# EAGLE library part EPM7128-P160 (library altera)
EPM70128 MAX 7000 family
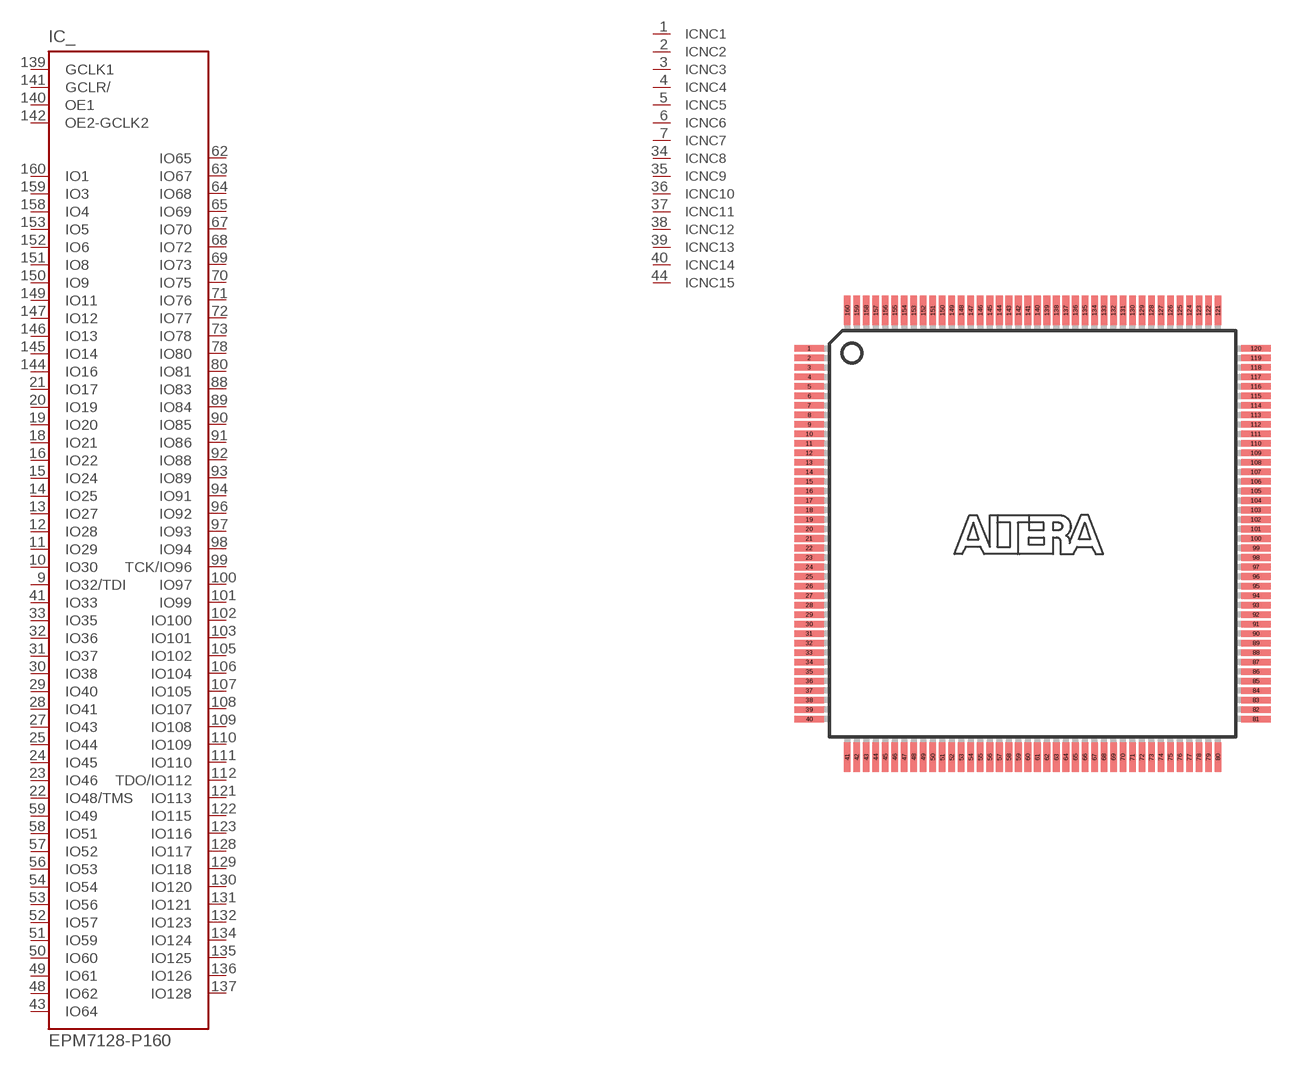
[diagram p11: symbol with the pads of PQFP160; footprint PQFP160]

Designator prefix IC; gates _=EPM7128 NC1=NC NC2=NC NC3=NC NC4=NC NC5=NC NC6=NC NC7=NC NC8=NC NC9=NC NC10=NC NC11=NC NC12=NC NC13=NC NC14=NC NC15=NC NC16=NC NC17=NC NC18=NC NC19=NC NC20=NC NC21=NC NC22=NC NC23=NC NC24=NC NC25=NC NC26=NC NC27=NC NC28=NC NC29=NC NC30=NC NC31=NC NC32=NC NC33=NC NC34=NC NC35=NC NC36=NC NC37=NC NC38=NC NC39=NC NC40=NC NC41=NC NC42=NC NC43=NC NC44=NC 1=VCC 2=VCC 3=VCCIO 4=VCCIO 5=VCCIO 6=VCCIO 7=VCCIO 8=VCCIO 9=GND 10=GND 11=GND 12=GND 13=GND 14=GND 15=GND 16=GND

## EPM7128-P160 (MPN: EPM7128SQC160-10N; OC_FARNELL: 1549435; OC_NEWARK: 51R9760)  [PQFP160]
1  NC1:NC  nc
2  NC2:NC  nc
3  NC3:NC  nc
4  NC4:NC  nc
5  NC5:NC  nc
6  NC6:NC  nc
7  NC7:NC  nc
8  3:VCCIO  pwr
9  _:IO32/TDI
10  _:IO30
11  _:IO29
12  _:IO28
13  _:IO27
14  _:IO25
15  _:IO24
16  _:IO22
17  9:GND  pwr
18  _:IO21
19  _:IO20
20  _:IO19
21  _:IO17
22  _:IO48/TMS
23  _:IO46
24  _:IO45
25  _:IO44
26  4:VCCIO  pwr
27  _:IO43
28  _:IO41
29  _:IO40
30  _:IO38
31  _:IO37
32  _:IO36
33  _:IO35
34  NC8:NC  nc
35  NC9:NC  nc
36  NC10:NC  nc
37  NC11:NC  nc
38  NC12:NC  nc
39  NC13:NC  nc
40  NC14:NC  nc
41  _:IO33
42  10:GND  pwr
43  _:IO64
44  NC15:NC  nc
45  NC16:NC  nc
46  NC17:NC  nc
47  NC18:NC  nc
48  _:IO62
49  _:IO61
50  _:IO60
51  _:IO59
52  _:IO57
53  _:IO56
54  _:IO54
55  5:VCCIO  pwr
56  _:IO53
57  _:IO52
58  _:IO51
59  _:IO49
60  11:GND  pwr
61  1:VCC  pwr
62  _:IO65
63  _:IO67
64  _:IO68
65  _:IO69
66  12:GND  pwr
67  _:IO70
68  _:IO72
69  _:IO73
70  _:IO75
71  _:IO76
72  _:IO77
73  _:IO78
74  NC19:NC  nc
75  NC20:NC  nc
76  NC21:NC  nc
77  NC22:NC  nc
78  _:IO80
79  6:VCCIO  pwr
80  _:IO81
81  NC23:NC  nc
82  NC24:NC  nc
83  NC25:NC  nc
84  NC26:NC  nc
85  NC27:NC  nc
86  NC28:NC  nc
87  NC29:NC  nc
88  _:IO83
89  _:IO84
90  _:IO85
91  _:IO86
92  _:IO88
93  _:IO89
94  _:IO91
95  13:GND  pwr
96  _:IO92
97  _:IO93
98  _:IO94
99  _:TCK/IO96
100  _:IO97
101  _:IO99
102  _:IO100
103  _:IO101
104  7:VCCIO  pwr
105  _:IO102
106  _:IO104
107  _:IO105
108  _:IO107
109  _:IO108
110  _:IO109
111  _:IO110
112  _:TDO/IO112
113  14:GND  pwr
114  NC30:NC  nc
115  NC31:NC  nc
116  NC32:NC  nc
117  NC33:NC  nc
118  NC34:NC  nc
119  NC35:NC  nc
120  NC36:NC  nc
121  _:IO113
122  _:IO115
123  _:IO116
124  NC37:NC  nc
125  NC38:NC  nc
126  NC39:NC  nc
127  NC40:NC  nc
128  _:IO117
129  _:IO118
130  _:IO120
131  _:IO121
132  _:IO123
133  8:VCCIO  pwr
134  _:IO124
135  _:IO125
136  _:IO126
137  _:IO128
138  16:GND  pwr
139  _:GCLK1  in
140  _:OE1  in
141  _:GCLR/  in
142  _:OE2-GCLK2  in
143  2:VCC  pwr
144  _:IO16
145  _:IO14
146  _:IO13
147  _:IO12
148  15:GND  pwr
149  _:IO11
150  _:IO9
151  _:IO8
152  _:IO6
153  _:IO5
154  NC41:NC  nc
155  NC42:NC  nc
156  NC43:NC  nc
157  NC44:NC  nc
158  _:IO4
159  _:IO3
160  _:IO1

## Footprint PQFP160 (pad centres in mm)
Plastic Quad Flat Pack
smd 2 x 0.45: 1 -15.275,12.675; 2 -15.275,12.025; 3 -15.275,11.375; 4 -15.275,10.725; 5 -15.275,10.075; 6 -15.275,9.425; 7 -15.275,8.775; 8 -15.275,8.125; 9 -15.275,7.475; 10 -15.275,6.825; 11 -15.275,6.175; 12 -15.275,5.525; 13 -15.275,4.875; 14 -15.275,4.225; 15 -15.275,3.575; 16 -15.275,2.925; 17 -15.275,2.275; 18 -15.275,1.625; 19 -15.275,0.975; 20 -15.275,0.325; 21 -15.275,-0.325; 22 -15.275,-0.975; 23 -15.275,-1.625; 24 -15.275,-2.275; 25 -15.275,-2.925; 26 -15.275,-3.575; 27 -15.275,-4.225; 28 -15.275,-4.875; 29 -15.275,-5.525; 30 -15.275,-6.175; 31 -15.275,-6.825; 32 -15.275,-7.475; 33 -15.275,-8.125; 34 -15.275,-8.775; 35 -15.275,-9.425; 36 -15.275,-10.075; 37 -15.275,-10.725; 38 -15.275,-11.375; 39 -15.275,-12.025; 40 -15.275,-12.675; 81 15.275,-12.675; 82 15.275,-12.025; 83 15.275,-11.375; 84 15.275,-10.725; 85 15.275,-10.075; 86 15.275,-9.425; 87 15.275,-8.775; 88 15.275,-8.125; 89 15.275,-7.475; 90 15.275,-6.825; 91 15.275,-6.175; 92 15.275,-5.525; 93 15.275,-4.875; 94 15.275,-4.225; 95 15.275,-3.575; 96 15.275,-2.925; 97 15.275,-2.275; 98 15.275,-1.625; 99 15.275,-0.975; 100 15.275,-0.325; 101 15.275,0.325; 102 15.275,0.975; 103 15.275,1.625; 104 15.275,2.275; 105 15.275,2.925; 106 15.275,3.575; 107 15.275,4.225; 108 15.275,4.875; 109 15.275,5.525; 110 15.275,6.175; 111 15.275,6.825; 112 15.275,7.475; 113 15.275,8.125; 114 15.275,8.775; 115 15.275,9.425; 116 15.275,10.075; 117 15.275,10.725; 118 15.275,11.375; 119 15.275,12.025; 120 15.275,12.675
smd 0.45 x 2: 41 -12.675,-15.275; 42 -12.025,-15.275; 43 -11.375,-15.275; 44 -10.725,-15.275; 45 -10.075,-15.275; 46 -9.425,-15.275; 47 -8.775,-15.275; 48 -8.125,-15.275; 49 -7.475,-15.275; 50 -6.825,-15.275; 51 -6.175,-15.275; 52 -5.525,-15.275; 53 -4.875,-15.275; 54 -4.225,-15.275; 55 -3.575,-15.275; 56 -2.925,-15.275; 57 -2.275,-15.275; 58 -1.625,-15.275; 59 -0.975,-15.275; 60 -0.325,-15.275; 61 0.325,-15.275; 62 0.975,-15.275; 63 1.625,-15.275; 64 2.275,-15.275; 65 2.925,-15.275; 66 3.575,-15.275; 67 4.225,-15.275; 68 4.875,-15.275; 69 5.525,-15.275; 70 6.175,-15.275; 71 6.825,-15.275; 72 7.475,-15.275; 73 8.125,-15.275; 74 8.775,-15.275; 75 9.425,-15.275; 76 10.075,-15.275; 77 10.725,-15.275; 78 11.375,-15.275; 79 12.025,-15.275; 80 12.675,-15.275; 121 12.675,15.275; 122 12.025,15.275; 123 11.375,15.275; 124 10.725,15.275; 125 10.075,15.275; 126 9.425,15.275; 127 8.775,15.275; 128 8.125,15.275; 129 7.475,15.275; 130 6.825,15.275; 131 6.175,15.275; 132 5.525,15.275; 133 4.875,15.275; 134 4.225,15.275; 135 3.575,15.275; 136 2.925,15.275; 137 2.275,15.275; 138 1.625,15.275; 139 0.975,15.275; 140 0.325,15.275; 141 -0.325,15.275; 142 -0.975,15.275; 143 -1.625,15.275; 144 -2.275,15.275; 145 -2.925,15.275; 146 -3.575,15.275; 147 -4.225,15.275; 148 -4.875,15.275; 149 -5.525,15.275; 150 -6.175,15.275; 151 -6.825,15.275; 152 -7.475,15.275; 153 -8.125,15.275; 154 -8.775,15.275; 155 -9.425,15.275; 156 -10.075,15.275; 157 -10.725,15.275; 158 -11.375,15.275; 159 -12.025,15.275; 160 -12.675,15.275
